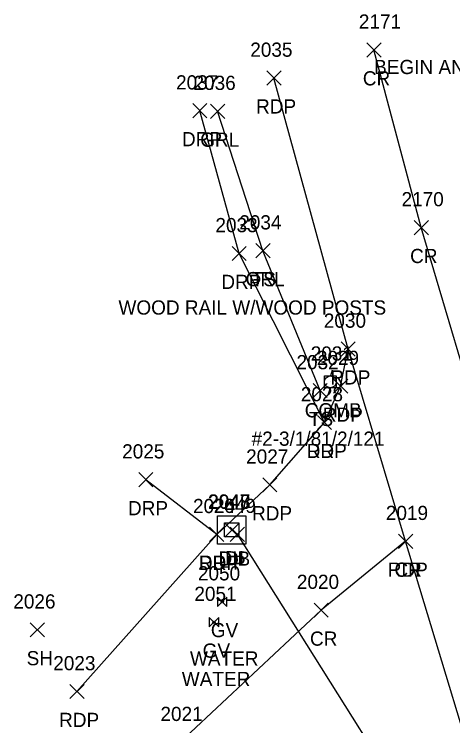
# Model space of a CAD drawing. Extents: x 1620157 to 1620595, y 115111 to 117885.
# Drawn here: x 1620156.8 to 1620218.6, y 115746 to 115846.2 of the extents above; entities that cross this region are included whole.
import ezdxf

# ---------------------------------------------------------------- set-up
doc = ezdxf.new("R2010")
doc.units = 0
for name, color, linetype in [('D_A', 7, 'Continuous'), ('D_I', 7, 'Continuous'), ('D_TIC', 7, 'Continuous'), ('DCP', 7, 'Continuous'), ('DS', 7, 'Continuous'), ('L_A', 7, 'Continuous'), ('L_I', 7, 'Continuous'), ('L_TIC', 7, 'Continuous'), ('LELB', 7, 'Continuous'), ('P_A', 7, 'Continuous'), ('P_I', 7, 'Continuous'), ('P_TIC', 7, 'Continuous'), ('PET', 7, 'Continuous'), ('PRC', 7, 'Continuous'), ('R_A', 7, 'Continuous'), ('R_C', 7, 'Continuous'), ('R_I', 7, 'Continuous'), ('R_TIC', 7, 'Continuous'), ('RDP', 7, 'Continuous'), ('RGR', 7, 'Continuous'), ('S_C', 7, 'Continuous'), ('U_A', 7, 'Continuous'), ('U_C', 7, 'Continuous'), ('U_I', 7, 'Continuous'), ('UP', 7, 'Continuous'), ('UWV', 7, 'Continuous')]:
    doc.layers.add(name, color=color, linetype=linetype)

msp = doc.modelspace()

# ---------------------------------------------------------------- linework, layer by layer
at = {"layer": 'D_TIC'}
for points in [[(1620186.46, 115772.52), (1620188.46, 115774.52)], [(1620188.46, 115772.52), (1620186.46, 115774.52)], [(1620187.22, 115771.94), (1620189.22, 115773.94)], [(1620189.22, 115771.94), (1620187.22, 115773.94)]]:
    msp.add_lwpolyline(points, dxfattribs=at)
at = {"layer": 'DCP'}
msp.add_lwpolyline([(1620222.95, 115717.71), (1620188.22, 115772.94)], dxfattribs=at)
at = {"layer": 'DS'}
for p, q in [((1620185.41, 115775.56), (1620189.41, 115775.56)), ((1620185.41, 115771.56), (1620185.41, 115775.56)), ((1620189.41, 115775.56), (1620189.41, 115771.56)), ((1620186.41, 115772.56), (1620186.41, 115774.56)), ((1620186.41, 115774.56), (1620188.41, 115774.56)), ((1620188.41, 115774.56), (1620188.41, 115772.56)), ((1620187.41, 115773.56), (1620187.41, 115773.56)), ((1620187.41, 115773.56), (1620187.41, 115773.56)), ((1620188.41, 115772.56), (1620186.41, 115772.56)), ((1620189.41, 115771.56), (1620185.41, 115771.56))]:
    msp.add_line(p, q, dxfattribs=at)
at = {"layer": 'L_TIC'}
for points in [[(1620190.82, 115811.89), (1620192.82, 115813.89)], [(1620192.82, 115811.89), (1620190.82, 115813.89)], [(1620198.89, 115792.19), (1620200.89, 115794.19)], [(1620200.89, 115792.19), (1620198.89, 115794.19)], [(1620159.01, 115758.48), (1620161.01, 115760.48)], [(1620161.01, 115758.48), (1620159.01, 115760.48)]]:
    msp.add_lwpolyline(points, dxfattribs=at)
at = {"layer": 'LELB'}
msp.add_lwpolyline([(1620199.89, 115793.19), (1620191.82, 115812.89)], dxfattribs=at)
at = {"layer": 'P_TIC'}
for points in [[(1620206.47, 115840.18), (1620208.47, 115842.18)], [(1620208.47, 115840.18), (1620206.47, 115842.18)], [(1620192.37, 115836.22), (1620194.37, 115838.22)], [(1620194.37, 115836.22), (1620192.37, 115838.22)], [(1620213.14, 115815.15), (1620215.14, 115817.15)], [(1620215.14, 115815.15), (1620213.14, 115817.15)], [(1620202.83, 115798.04), (1620204.83, 115800.04)], [(1620204.83, 115798.04), (1620202.83, 115800.04)], [(1620202.83, 115798.04), (1620204.83, 115800.04)], [(1620204.83, 115798.04), (1620202.83, 115800.04)], [(1620201.77, 115792.8), (1620203.77, 115794.8)], [(1620203.77, 115792.8), (1620201.77, 115794.8)], [(1620199.5, 115787.68), (1620201.5, 115789.68)], [(1620201.5, 115787.68), (1620199.5, 115789.68)], [(1620191.79, 115778.9), (1620193.79, 115780.9)], [(1620193.79, 115778.9), (1620191.79, 115780.9)], [(1620184.3, 115771.92), (1620186.3, 115773.92)], [(1620186.3, 115771.92), (1620184.3, 115773.92)], [(1620210.93, 115770.95), (1620212.93, 115772.95)], [(1620212.93, 115770.95), (1620210.93, 115772.95)], [(1620210.93, 115770.95), (1620212.93, 115772.95)], [(1620212.93, 115770.95), (1620210.93, 115772.95)], [(1620199.02, 115761.24), (1620201.02, 115763.24)], [(1620201.02, 115761.24), (1620199.02, 115763.24)], [(1620164.59, 115749.78), (1620166.59, 115751.78)], [(1620166.59, 115749.78), (1620164.59, 115751.78)]]:
    msp.add_lwpolyline(points, dxfattribs=at)
at = {"layer": 'PET'}
for points in [[(1620320.14, 115439.39), (1620314.87, 115455.06), (1620309.06, 115464.39), (1620304.22, 115479.4), (1620297.09, 115496.09), (1620293.95, 115506.93), (1620292.02, 115512.47), (1620283.67, 115536.02), (1620274.58, 115564.81), (1620268.48, 115584.52), (1620253.11, 115635.23), (1620250.12, 115643.88), (1620242.65, 115668.01), (1620237.66, 115684.19), (1620235.08, 115693.76), (1620231.19, 115707.41), (1620225.41, 115727.43), (1620211.93, 115771.95), (1620203.83, 115799.04), (1620193.37, 115837.22)], [(1620165.59, 115750.78), (1620185.3, 115772.92), (1620192.79, 115779.9), (1620200.5, 115788.68), (1620202.77, 115793.8), (1620203.83, 115799.04)]]:
    msp.add_lwpolyline(points, dxfattribs=at)
at = {"layer": 'PRC'}
for points in [[(1620328.08, 115447.46), (1620322.14, 115466.61), (1620311.32, 115499.81), (1620303.78, 115522.91), (1620294.72, 115551.74), (1620279.31, 115600.23), (1620271.12, 115626.45), (1620257.91, 115669.49), (1620247.64, 115703.03), (1620242.45, 115719.65), (1620232.98, 115752.35), (1620223.66, 115784.04), (1620214.14, 115816.15), (1620207.47, 115841.18)], [(1620211.93, 115771.95), (1620200.02, 115762.24), (1620180.14, 115743.63), (1620164.84, 115729.05)]]:
    msp.add_lwpolyline(points, dxfattribs=at)
at = {"layer": 'R_TIC'}
for points in [[(1620181.91, 115831.61), (1620183.91, 115833.61)], [(1620183.91, 115831.61), (1620181.91, 115833.61)], [(1620184.43, 115831.54), (1620186.43, 115833.54)], [(1620186.43, 115831.54), (1620184.43, 115833.54)], [(1620190.82, 115811.89), (1620192.82, 115813.89)], [(1620192.82, 115811.89), (1620190.82, 115813.89)], [(1620187.46, 115811.5), (1620189.46, 115813.5)], [(1620189.46, 115811.5), (1620187.46, 115813.5)], [(1620199.5, 115787.68), (1620201.5, 115789.68)], [(1620201.5, 115787.68), (1620199.5, 115789.68)], [(1620174.3, 115779.62), (1620176.3, 115781.62)], [(1620176.3, 115779.62), (1620174.3, 115781.62)], [(1620184.3, 115771.92), (1620186.3, 115773.92)], [(1620186.3, 115771.92), (1620184.3, 115773.92)]]:
    msp.add_lwpolyline(points, dxfattribs=at)
at = {"layer": 'RDP'}
for points in [[(1620200.5, 115788.68), (1620188.46, 115812.5), (1620182.91, 115832.61)], [(1620185.3, 115772.92), (1620175.3, 115780.62)]]:
    msp.add_lwpolyline(points, dxfattribs=at)
at = {"layer": 'RGR'}
msp.add_lwpolyline([(1620191.82, 115812.89), (1620185.43, 115832.54)], dxfattribs=at)
at = {"layer": 'UP'}
for p, q in [((1620201.57, 115796.07), (1620201.32, 115795.24)), ((1620200.49, 115793.57), (1620200.49, 115795.24)), ((1620200.49, 115795.24), (1620202.15, 115795.24)), ((1620202.15, 115795.24), (1620202.15, 115793.57)), ((1620202.15, 115793.57), (1620200.49, 115793.57)), ((1620201.07, 115792.74), (1620201.32, 115793.57)), ((1620201.32, 115794.41), (1620201.32, 115794.41))]:
    msp.add_line(p, q, dxfattribs=at)
msp.add_circle((1620201.32, 115794.41), 0.833, dxfattribs=at)
at = {"layer": 'UWV'}
for p, q in [((1620185.41, 115764.1), (1620186.74, 115762.77)), ((1620186.74, 115764.1), (1620185.41, 115762.77)), ((1620184.25, 115761.22), (1620185.59, 115759.88)), ((1620185.59, 115761.22), (1620184.25, 115759.88))]:
    msp.add_line(p, q, dxfattribs=at)
for points in [[(1620185.41, 115764.1), (1620185.41, 115762.77)], [(1620186.74, 115762.77), (1620186.74, 115764.1)], [(1620184.25, 115761.22), (1620184.25, 115759.88)], [(1620185.59, 115759.88), (1620185.59, 115761.22)]]:
    msp.add_lwpolyline(points, dxfattribs=at)
for centre in [(1620186.07, 115763.44), (1620184.92, 115760.55)]:
    msp.add_circle(centre, 0.167, dxfattribs=at)

# ---------------------------------------------------------------- texts
at = {"layer": 'D_A'}
for s, p in [('DIB', (1620185.56, 115768.52)), ('DI', (1620186.47, 115768.56)), ('P', (1620187.59, 115767.94))]:
    msp.add_text(s, height=2, dxfattribs=at).set_placement(p)
at = {"layer": 'D_I'}
for s, p in [('2047', (1620184.07, 115776.56)), ('2048', (1620184.12, 115776.52)), ('2049', (1620184.87, 115775.94))]:
    msp.add_text(s, height=2, dxfattribs=at).set_placement(p)
at = {"layer": 'L_A'}
for s, p in [('TS', (1620190.23, 115807.89)), ('TS', (1620198.3, 115788.19)), ('SH', (1620158.5, 115754.48))]:
    msp.add_text(s, height=2, dxfattribs=at).set_placement(p)
at = {"layer": 'L_I'}
for s, p in [('2034', (1620188.48, 115815.89)), ('2032', (1620196.55, 115796.19)), ('2026', (1620156.62, 115762.48))]:
    msp.add_text(s, height=2, dxfattribs=at).set_placement(p)
at = {"layer": 'P_A'}
for s, p in [('CR', (1620205.9, 115836.18)), ('RDP', (1620190.85, 115832.22)), ('CR', (1620212.57, 115811.15)), ('RDP', (1620201.32, 115794.04)), ('RDP', (1620201.32, 115794.04)), ('RDP', (1620200.26, 115788.8)), ('RDP', (1620197.99, 115783.68)), ('RDP', (1620190.28, 115774.9)), ('RDP', (1620182.79, 115767.92)), ('RDP', (1620209.42, 115766.95)), ('CR', (1620210.36, 115766.95)), ('CR', (1620198.45, 115757.24)), ('RDP', (1620163.08, 115745.78))]:
    msp.add_text(s, height=2, dxfattribs=at).set_placement(p)
at = {"layer": 'P_I'}
for s, p in [('2171', (1620205.34, 115844.18)), ('2035', (1620190.03, 115840.22)), ('2170', (1620211.36, 115819.15)), ('2030', (1620200.4, 115802.04)), ('2030', (1620200.4, 115802.04)), ('2029', (1620199.42, 115796.8)), ('2028', (1620197.16, 115791.68)), ('2027', (1620189.45, 115782.9)), ('2024', (1620181.96, 115775.92)), ('2019', (1620209.15, 115774.95)), ('2019', (1620209.15, 115774.95)), ('2020', (1620196.6, 115765.24)), ('2023', (1620162.25, 115753.78)), ('2021', (1620177.37, 115746.63))]:
    msp.add_text(s, height=2, dxfattribs=at).set_placement(p)
at = {"layer": 'R_A'}
for s, p in [('DRP', (1620180.4, 115827.61)), ('GRL', (1620182.97, 115827.54)), ('GRL', (1620189.37, 115807.89)), ('DRP', (1620185.95, 115807.5)), ('DRP', (1620197.99, 115783.68)), ('DRP', (1620172.79, 115775.62)), ('DRP', (1620182.79, 115767.92))]:
    msp.add_text(s, height=2, dxfattribs=at).set_placement(p)
at = {"layer": 'R_C'}
msp.add_text('WOOD RAIL W/WOOD POSTS', height=2, dxfattribs=at).set_placement((1620171.45, 115803.89))
at = {"layer": 'R_I'}
for s, p in [('2037', (1620179.57, 115835.61)), ('2036', (1620182.03, 115835.54)), ('2034', (1620188.48, 115815.89)), ('2033', (1620185.12, 115815.5)), ('2028', (1620197.16, 115791.68)), ('2025', (1620171.97, 115783.62)), ('2024', (1620181.96, 115775.92))]:
    msp.add_text(s, height=2, dxfattribs=at).set_placement(p)
at = {"layer": 'S_C'}
msp.add_text('BEGIN AND END NO PARKING', height=2, dxfattribs=at).set_placement((1620207.5, 115837.78))
at = {"layer": 'U_A'}
for s, p in [('COMB', (1620197.71, 115789.41)), ('GV', (1620184.47, 115758.44)), ('GV', (1620183.32, 115755.55))]:
    msp.add_text(s, height=2, dxfattribs=at).set_placement(p)
at = {"layer": 'U_C'}
for s, p in [('#2-3/1/81/2/121', (1620190.22, 115785.41)), ('WATER', (1620181.53, 115754.44)), ('WATER', (1620180.38, 115751.55))]:
    msp.add_text(s, height=2, dxfattribs=at).set_placement(p)
at = {"layer": 'U_I'}
for s, p in [('2031', (1620198.55, 115797.41)), ('2050', (1620182.65, 115766.44)), ('2051', (1620182.15, 115763.55))]:
    msp.add_text(s, height=2, dxfattribs=at).set_placement(p)

doc.saveas('drawing.dxf')
